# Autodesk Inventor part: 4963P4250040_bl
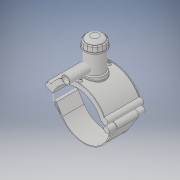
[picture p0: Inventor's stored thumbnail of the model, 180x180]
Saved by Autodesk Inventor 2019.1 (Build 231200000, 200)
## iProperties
Created: 2017-07
Part Number: 4963P4250040_bl
Material: Generic
Document SubType Name: Modeling
Designer: KIM
Density: 1 g/cm^3
Appearance: Default
Author: KIM
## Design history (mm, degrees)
derived "4963P4.ipt"
feature "Solid1::4963P4.ipt" dims "ScaleForDerivedMember" = 10
feature "Solid2::4963P4.ipt" dims "ScaleForDerivedMember" = 10
feature "Solid3::4963P4.ipt" dims "ScaleForDerivedMember" = 10
tag "TaggingFeature1"
body "Solid1"
body "Solid2"
body "Solid3"
other parameters: "B_" = 252 [user parameter], "L_" = 176 [user parameter], "d_t" = 6 [user parameter], "H_2" = 177 [user parameter], "H_" = 142 [user parameter], "d148" = 3.75 [user parameter], "d160" = 3.75 [user parameter], "d169" = 3.75 [user parameter], "d192" = 8 [user parameter], "d2" = 327.6 [user parameter], "d3" = 62.5 [user parameter], "d4" = 176 [user parameter], "d5" = 0 [user parameter], "d6" = 0.1 [user parameter], "d8" = 0 [user parameter], "d19" = 6 [user parameter], "d20" = 6 [user parameter], "d21" = 105.6 [user parameter], "d23" = 0 [user parameter], "d24" = 52.8 [user parameter], "d26" = 0 [user parameter], "d27" = 3 [user parameter], "d28" = 3 [user parameter], "d29" = 3 [user parameter], "d30" = 83.33333 [user parameter], "d31" = 6 [user parameter], "d32" = 0 [user parameter], "d33" = 0 [user parameter], "d34" = 0.6 [user parameter], "d40" = 150.8 [user parameter], "d43" = 0 [user parameter], "d45" = 0 [user parameter], "d47" = 250.6 [user parameter], "d70" = 15 [user parameter], "d72" = 0 [user parameter], "d73" = 6 [user parameter], "d75" = 5 [user parameter], "d76" = 0 [user parameter], "d77" = 12.5 [user parameter], "d78" = 155 [user parameter], "d79" = 15 [user parameter], "d80" = 70.4 [user parameter], "d82" = 5 deg [user parameter], "d84" = 4 [user parameter], "d85" = 14 [user parameter], "d86" = 0 [user parameter], "d87" = 3 [user parameter], "d88" = 0 [user parameter], "d89" = 1 [user parameter], "d90" = 1 [user parameter], "d91" = 140.8 [user parameter], "d92" = 0 [user parameter], "d93" = 0.5 [user parameter], "d94" = 131.57895 [user parameter], "d96" = 295.8 [user parameter], "d97" = 3.52 [user parameter], "d98" = 0 [user parameter], "d102" = 2.5 [user parameter], "d120" = 140 deg [user parameter], "d121" = 24.228 [user parameter], "d122" = 20 deg [user parameter], "d124" = 174 [user parameter], "d126" = 0 [user parameter], "d143" = 257.5 [user parameter], "d145" = 30.76923 [user parameter], "d149" = 3.75 [user parameter], "d150" = 33.84615 [user parameter], "d153" = 176 [user parameter], "d154" = 0 [user parameter], "d156" = 145 [user parameter], "d157" = 160 deg [user parameter], "d159" = 8 [user parameter], "d161" = 3.75 [user parameter], "d162" = 105.6 [user parameter], "d163" = 0 [user parameter], "d164" = 125 [user parameter], "d167" = 25 [user parameter], "d168" = 141.46341 [user parameter], "d170" = 3.75 [user parameter], "d172" = 0 [user parameter], "d173" = 1 [user parameter], "d175" = 125 [user parameter], "d176" = 20 deg [user parameter], "d177" = 17.5 [user parameter], "d180" = 0 [user parameter], "d183" = 16 [user parameter], "d184" = 14 [user parameter], "d185" = 57.2 [user parameter], "d186" = 57.2 [user parameter], "d187" = 145 [user parameter], "d188" = 12 [user parameter], "d189" = 17.5 [user parameter], "d190" = 0 [user parameter], "d191" = 217.5 [user parameter], "d193" = 8 [user parameter], "d194" = 6.16 [user parameter], "d195" = 90 deg [user parameter], "d197" = 0 [user parameter], "d199" = 0 [user parameter], "d202" = 0 [user parameter], "d203" = 177 [user parameter], "d204" = 95 [user parameter], "d206" = 85 [user parameter], "d207" = 132.75 [user parameter], "d208" = 138.06 [user parameter], "d209" = 164.61 [user parameter], "d210" = 86 [user parameter], "d213" = 36 [user parameter], "d216" = 0 [user parameter], "d217" = 25 [user parameter], "d218" = 25 [user parameter], "d219" = 5 [user parameter], "d224" = 0 [user parameter], "d227" = 32 [user parameter], "d228" = 142 [user parameter], "d230" = 5 [user parameter]
